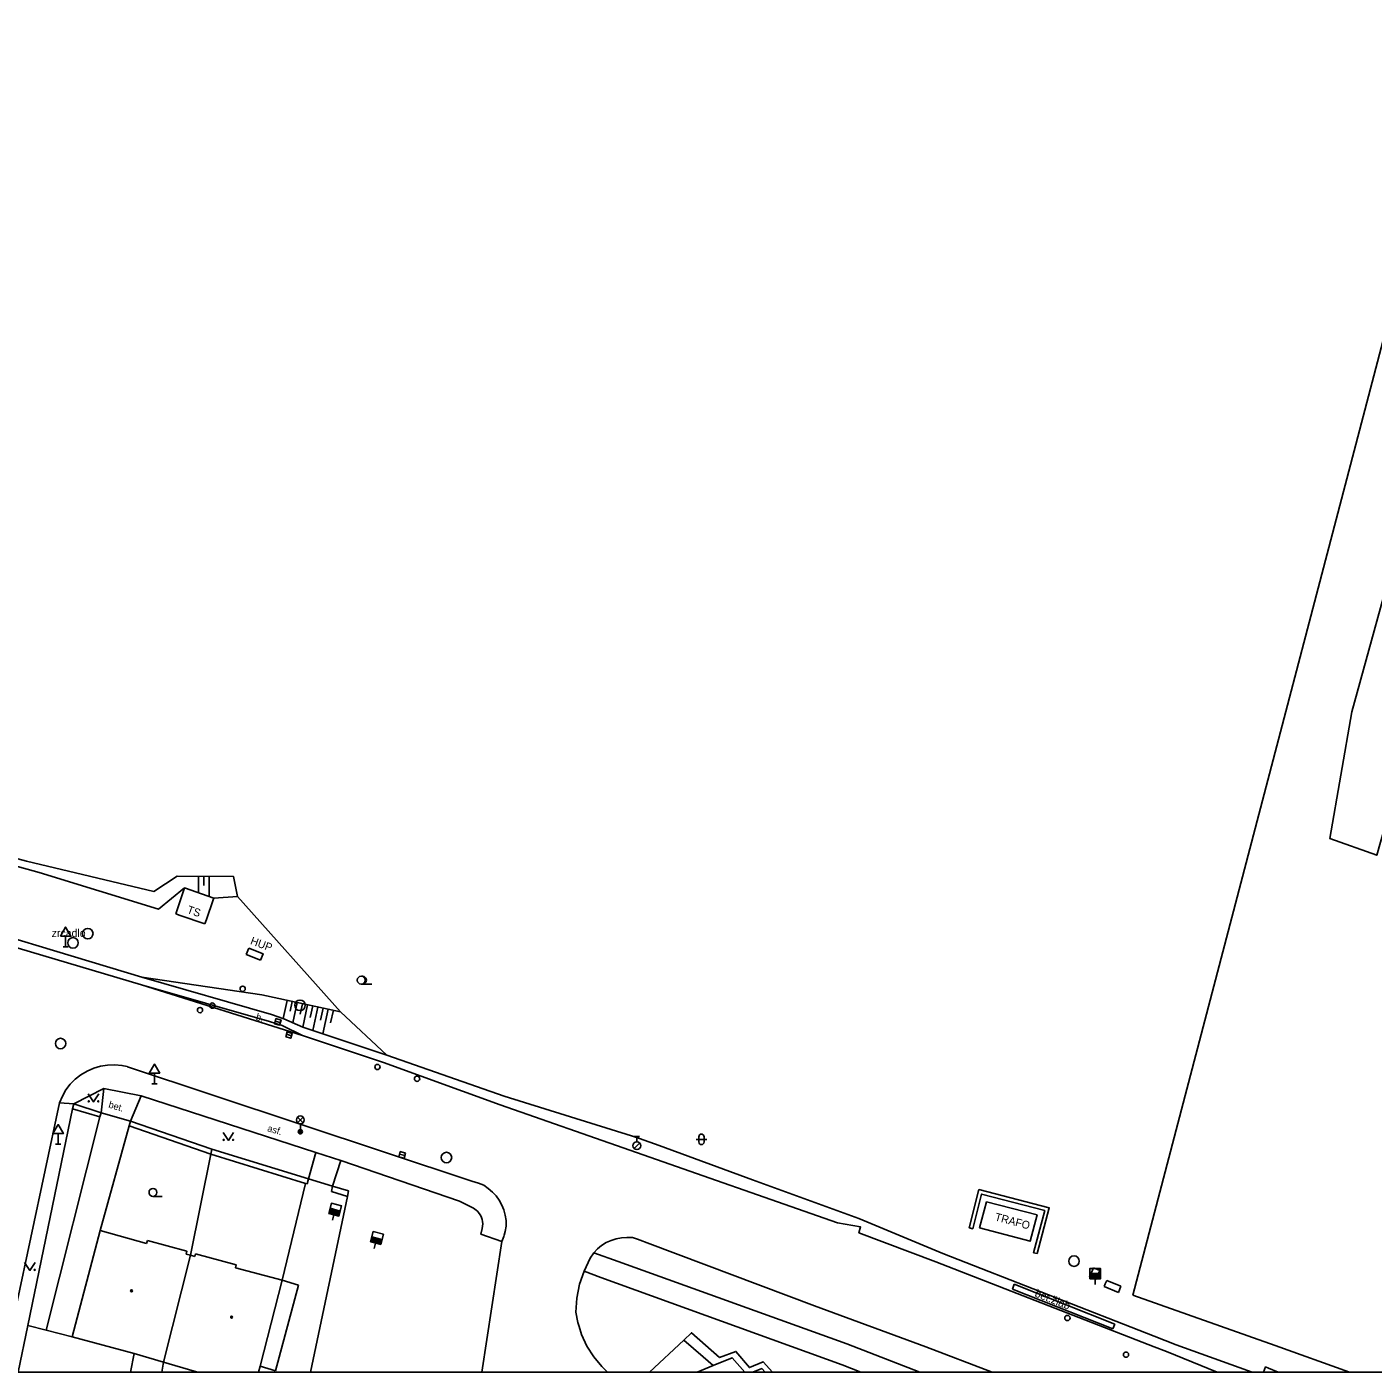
# Model space of a CAD drawing. Extents: x -599951 to -598963, y -1164095 to -1162939.
# Drawn here: x -599607.3 to -599479.2, y -1164094.7 to -1163966.7 of the extents above; entities that cross this region are included whole.
import ezdxf

# ---------------------------------------------------------------- set-up
doc = ezdxf.new("R2010")
doc.units = 0
for name, color, linetype in [('Level 10', 7, 'Continuous'), ('Level 11', 7, 'Continuous'), ('Level 14', 7, 'Continuous'), ('Level 15', 7, 'Continuous'), ('Level 21', 7, 'Continuous'), ('Level 24', 7, 'Continuous'), ('Level 27', 7, 'Continuous'), ('Level 28', 7, 'Continuous'), ('Level 33', 7, 'Continuous'), ('Level 34', 7, 'Continuous'), ('Level 36', 7, 'Continuous'), ('Level 39', 7, 'Continuous'), ('Level 40', 7, 'Continuous'), ('Level 41', 7, 'Continuous'), ('Level 42', 7, 'Continuous'), ('Level 5', 7, 'Continuous'), ('Level 6', 7, 'Continuous'), ('Level 7', 7, 'Continuous'), ('Level 8', 7, 'Continuous'), ('Vrstva 53', 7, 'Continuous')]:
    doc.layers.add(name, color=color, linetype=linetype)

msp = doc.modelspace()

# ---------------------------------------------------------------- linework, layer by layer
at = {"layer": 'Level 10'}
for p, q in [((-599609.64, -1164094.69), (-599604.19, -1164069.07)), ((-599563.98, -1164094.69), (-599562.08, -1164082.28))]:
    msp.add_line(p, q, dxfattribs=at)
for points in [[(-599638.89, -1164045.17), (-599617.56, -1164051.55), (-599596.39, -1164057.85), (-599581.06, -1164062.67), (-599573.37, -1164065.22)], [(-599604.19, -1164069.07), (-599603.92, -1164068.44), (-599603.58, -1164067.85), (-599603.17, -1164067.31), (-599602.69, -1164066.82), (-599602.15, -1164066.4), (-599601.57, -1164066.05), (-599600.94, -1164065.78), (-599600.29, -1164065.59), (-599599.61, -1164065.48), (-599598.93, -1164065.46)], [(-599598.93, -1164065.46), (-599598.25, -1164065.52), (-599597.76, -1164065.62), (-599597.71, -1164065.64), (-599564.95, -1164076.52), (-599564.31, -1164076.73), (-599563.81, -1164076.92)], [(-599573.37, -1164065.22), (-599562.25, -1164069.26), (-599549.91, -1164073.58), (-599530.13, -1164080.49), (-599527.95, -1164080.88), (-599528.11, -1164081.43), (-599520.79, -1164084.2), (-599500, -1164092.28), (-599498.82, -1164092.74), (-599494.02, -1164094.69)], [(-599563.81, -1164076.92), (-599563.38, -1164077.23), (-599562.98, -1164077.56), (-599562.63, -1164077.93), (-599562.33, -1164078.35), (-599562.08, -1164078.8), (-599561.89, -1164079.27), (-599561.76, -1164079.77), (-599561.69, -1164080.28), (-599561.69, -1164080.8), (-599561.76, -1164081.31), (-599561.86, -1164081.68), (-599561.89, -1164081.8), (-599562.08, -1164082.28)], [(-599553.35, -1164083.34), (-599553, -1164082.97), (-599552.6, -1164082.65), (-599552.16, -1164082.38), (-599551.7, -1164082.17), (-599551.21, -1164082.02), (-599550.7, -1164081.93), (-599550.19, -1164081.9), (-599549.66, -1164081.9)], [(-599515.43, -1164094.69), (-599521.74, -1164092.28), (-599532.33, -1164088.4), (-599547.99, -1164082.49), (-599549.19, -1164082.04), (-599549.66, -1164081.9)], [(-599554.27, -1164085.1), (-599553.67, -1164083.87), (-599553.35, -1164083.34)], [(-599554.27, -1164085.1), (-599554.69, -1164086.34), (-599554.95, -1164087.65), (-599555.05, -1164088.98), (-599554.86, -1164089.97), (-599554.74, -1164090.36), (-599554.5, -1164091.12), (-599553.99, -1164092.22), (-599553.35, -1164093.24), (-599552.58, -1164094.18), (-599552.04, -1164094.69)]]:
    msp.add_lwpolyline(points, dxfattribs=at)
at = {"layer": 'Level 11'}
for p, q in [((-599548.05, -1164094.69), (-599544.77, -1164091.65)), ((-599543.5, -1164094.69), (-599541.97, -1164094.07)), ((-599489.12, -1164094.32), (-599488.19, -1164094.69))]:
    msp.add_line(p, q, dxfattribs=at)
for points in [[(-599477.64, -1164041.35), (-599478.82, -1164045.51), (-599483.27, -1164043.92), (-599481.2, -1164031.86), (-599476.6, -1164015.19), (-599469.61, -1163987.57), (-599469.77, -1163986.77), (-599466.12, -1163972.33)], [(-599596.35, -1164057.12), (-599617.6, -1164050.7), (-599625.85, -1164047.89), (-599634, -1164045.88), (-599638.54, -1164044.56), (-599660.54, -1164037.91), (-599660.28, -1164036.8), (-599661.4, -1164036.53), (-599661.73, -1164037.61), (-599663.03, -1164037.18), (-599677.51, -1164032.87)], [(-599596.35, -1164057.12), (-599584.02, -1164060.68), (-599582.83, -1164061.07), (-599581.03, -1164061.88)], [(-599596.39, -1164057.85), (-599584.21, -1164061.33), (-599583.01, -1164061.7), (-599581.06, -1164062.67)], [(-599581.03, -1164061.88), (-599573.05, -1164064.54)], [(-599490.68, -1164094.69), (-599491.12, -1164094.53), (-599497.91, -1164092.1), (-599500, -1164091.28), (-599520.12, -1164083.41), (-599528.11, -1164080.07), (-599538.23, -1164076.39), (-599547.12, -1164073.14), (-599548.98, -1164072.47), (-599549.76, -1164072.22), (-599561.87, -1164068.45), (-599573.05, -1164064.54)], [(-599602.84, -1164069.18), (-599599.98, -1164067.7)], [(-599599.98, -1164067.7), (-599600.24, -1164070.02)], [(-599596.42, -1164068.41), (-599599.98, -1164067.7)], [(-599597.44, -1164070.83), (-599596.42, -1164068.41)], [(-599579.81, -1164073.79), (-599596.42, -1164068.41)], [(-599602.84, -1164069.18), (-599604.19, -1164069.07)], [(-599600.34, -1164070.42), (-599605.46, -1164090.71)], [(-599600.33, -1164081.21), (-599597.55, -1164071.25)], [(-599589.71, -1164073.49), (-599589.8, -1164073.96)], [(-599580.5, -1164076.3), (-599579.81, -1164073.79)], [(-599577.42, -1164074.55), (-599579.81, -1164073.79)], [(-599577.42, -1164074.55), (-599578.2, -1164077)], [(-599562.08, -1164082.28), (-599564.09, -1164081.57), (-599563.96, -1164081.02), (-599563.92, -1164080.81), (-599563.91, -1164080.6), (-599563.92, -1164080.38), (-599563.96, -1164080.17), (-599564.03, -1164079.97), (-599564.12, -1164079.77), (-599564.24, -1164079.59), (-599564.37, -1164079.43), (-599564.53, -1164079.28), (-599564.79, -1164079.11), (-599566.13, -1164078.44), (-599577.42, -1164074.55)], [(-599580.77, -1164076.75), (-599582.99, -1164085.96)], [(-599511.14, -1164083.42), (-599509.99, -1164079.07), (-599516.68, -1164077.33), (-599517.61, -1164080.97)], [(-599553.35, -1164083.34), (-599551.02, -1164084.18), (-599529.24, -1164092.02), (-599522.31, -1164094.69)], [(-599527.92, -1164094.69), (-599529.71, -1164094.01), (-599552.68, -1164085.68), (-599554.27, -1164085.1)], [(-599506.15, -1164085.65), (-599505.77, -1164084.77)], [(-599505.77, -1164084.77), (-599505.17, -1164085.02)], [(-599505.17, -1164085.02), (-599505.55, -1164085.9)], [(-599582.99, -1164085.96), (-599585.1, -1164094.12)], [(-599513.33, -1164086.32), (-599513.48, -1164086.79)], [(-599503.74, -1164090.13), (-599513.33, -1164086.32)], [(-599505.55, -1164085.9), (-599506.15, -1164085.65)], [(-599513.48, -1164086.79), (-599503.92, -1164090.59)], [(-599502.02, -1164087.39), (-599488.48, -1164092.18), (-599481.4, -1164094.69)], [(-599607.21, -1164090.26), (-599605.46, -1164090.71), (-599602.98, -1164091.35)], [(-599503.74, -1164090.13), (-599503.92, -1164090.59)], [(-599541.36, -1164093.32), (-599544.04, -1164090.96), (-599544.77, -1164091.65)], [(-599544.77, -1164091.65), (-599542.94, -1164093.23), (-599541.97, -1164094.07)], [(-599536.32, -1164094.69), (-599537.22, -1164093.72), (-599538.52, -1164094.27), (-599539.81, -1164092.73), (-599541.36, -1164093.32)], [(-599541.97, -1164094.07), (-599540.18, -1164093.33), (-599538.96, -1164094.69)], [(-599538.19, -1164094.69), (-599537.33, -1164094.36), (-599537.02, -1164094.69)], [(-599489.59, -1164094.69), (-599489.4, -1164094.21), (-599489.12, -1164094.32)]]:
    msp.add_lwpolyline(points, dxfattribs=at)
at = {"layer": 'Level 14'}
for points in [[(-599587.26, -1164049.45), (-599587.64, -1164047.53), (-599593, -1164047.51), (-599595.2, -1164048.95), (-599607.33, -1164046.09), (-599623.03, -1164041.85), (-599630.68, -1164039.44), (-599631.31, -1164034.32), (-599634.48, -1164028.79), (-599654.8, -1164024.23), (-599656.89, -1164030.03), (-599659.52, -1164029.78), (-599661.32, -1164033.38), (-599670.35, -1164030.9), (-599677.62, -1164029.52), (-599680.11, -1164029.17)], [(-599660.28, -1164036.8), (-599658.89, -1164031.33), (-599656.17, -1164031.26), (-599653.98, -1164025.92), (-599637.13, -1164031.36), (-599632.73, -1164035.88), (-599630.79, -1164039.78), (-599623.09, -1164042.46), (-599606.14, -1164047.14), (-599594.76, -1164050.63), (-599592.29, -1164048.62)], [(-599589.51, -1164049.6), (-599587.26, -1164049.45)], [(-599596.35, -1164057.12), (-599584.92, -1164058.81), (-599577.45, -1164060.42)]]:
    msp.add_lwpolyline(points, dxfattribs=at)
at = {"layer": 'Level 15'}
for points in [[(-599590.95, -1164047.52), (-599590.96, -1164049.09)], [(-599590.45, -1164047.52), (-599590.45, -1164048.39)], [(-599589.95, -1164047.52), (-599589.96, -1164049.44)], [(-599582.53, -1164059.32), (-599582.9, -1164061.05)], [(-599582.04, -1164059.43), (-599582.24, -1164060.34)], [(-599581.56, -1164059.54), (-599581.97, -1164061.46)], [(-599581.07, -1164059.64), (-599581.29, -1164060.65)], [(-599580.58, -1164059.75), (-599581.04, -1164061.88)], [(-599580.09, -1164059.85), (-599580.33, -1164060.94)], [(-599579.6, -1164059.96), (-599580.08, -1164062.2)], [(-599579.11, -1164060.06), (-599579.36, -1164061.21)], [(-599578.62, -1164060.17), (-599579.13, -1164062.51)], [(-599578.13, -1164060.27), (-599578.39, -1164061.47)]]:
    msp.add_lwpolyline(points, dxfattribs=at)
at = {"layer": 'Level 21'}
for points in [[(-599587.26, -1164049.45), (-599577.45, -1164060.42)], [(-599577.45, -1164060.42), (-599573.05, -1164064.54)]]:
    msp.add_lwpolyline(points, dxfattribs=at)
at = {"layer": 'Level 24'}
for points in [[(-599586.18, -1164054.36), (-599586.43, -1164054.96)], [(-599586.18, -1164054.36), (-599584.82, -1164054.88), (-599585.07, -1164055.51)], [(-599586.43, -1164054.96), (-599585.07, -1164055.51)], [(-599504.76, -1164086.55), (-599504.66, -1164086.3)], [(-599503.41, -1164087.11), (-599504.76, -1164086.55)], [(-599504.66, -1164086.3), (-599504.52, -1164085.97)], [(-599504.52, -1164085.97), (-599503.17, -1164086.53)], [(-599503.17, -1164086.53), (-599503.31, -1164086.86)], [(-599503.31, -1164086.86), (-599503.41, -1164087.11)]]:
    msp.add_lwpolyline(points, dxfattribs=at)
at = {"layer": 'Level 27'}
for p, q in [((-599583.66, -1164061.3), (-599583.18, -1164061.44)), ((-599582.59, -1164062.55), (-599582.11, -1164062.69)), ((-599571.82, -1164073.96), (-599571.34, -1164074.1))]:
    msp.add_line(p, q, dxfattribs=at)
for points in [[(-599583.73, -1164061.54), (-599583.25, -1164061.68), (-599583.11, -1164061.2), (-599583.59, -1164061.06)], [(-599582.66, -1164062.78), (-599582.19, -1164062.93), (-599582.04, -1164062.46), (-599582.51, -1164062.31)], [(-599571.89, -1164074.21), (-599571.4, -1164074.34), (-599571.27, -1164073.85), (-599571.76, -1164073.72)]]:
    msp.add_lwpolyline(points, close=True, dxfattribs=at)
for centre in [(-599602.91, -1164053.85), (-599601.5, -1164052.97), (-599581.3, -1164059.79), (-599604.09, -1164063.43), (-599567.36, -1164074.28), (-599507.63, -1164084.14)]:
    msp.add_circle(centre, 0.5, dxfattribs=at)
at = {"layer": 'Level 28'}
for p, q in [((-599549.49, -1164072.27), (-599548.99, -1164072.27)), ((-599549.24, -1164072.77), (-599549.24, -1164072.27)), ((-599549.5, -1164073.42), (-599548.97, -1164072.89)), ((-599578.56, -1164079.55), (-599577.59, -1164079.8)), ((-599578.54, -1164079.5), (-599577.58, -1164079.75)), ((-599578.53, -1164079.45), (-599577.56, -1164079.7)), ((-599578.52, -1164079.4), (-599577.55, -1164079.66)), ((-599578.51, -1164079.36), (-599577.54, -1164079.61)), ((-599578.49, -1164079.31), (-599577.53, -1164079.56)), ((-599578.48, -1164079.26), (-599577.51, -1164079.51)), ((-599578.47, -1164079.21), (-599577.5, -1164079.46)), ((-599578.46, -1164079.16), (-599577.49, -1164079.41)), ((-599578.44, -1164079.11), (-599577.48, -1164079.37)), ((-599578.09, -1164079.72), (-599578.22, -1164080.24)), ((-599574.58, -1164082.25), (-599573.61, -1164082.5)), ((-599574.56, -1164082.2), (-599573.6, -1164082.45)), ((-599574.55, -1164082.15), (-599573.58, -1164082.41)), ((-599574.54, -1164082.1), (-599573.57, -1164082.36)), ((-599574.53, -1164082.06), (-599573.56, -1164082.31)), ((-599574.51, -1164082.01), (-599573.55, -1164082.26)), ((-599574.5, -1164081.96), (-599573.53, -1164082.21)), ((-599574.49, -1164081.91), (-599573.52, -1164082.16)), ((-599574.48, -1164081.86), (-599573.51, -1164082.11)), ((-599574.46, -1164081.81), (-599573.5, -1164082.07)), ((-599574.11, -1164082.42), (-599574.24, -1164082.94)), ((-599506.12, -1164085.33), (-599505.12, -1164085.33)), ((-599506.12, -1164085.38), (-599505.12, -1164085.38)), ((-599506.12, -1164085.43), (-599505.12, -1164085.43)), ((-599506.12, -1164085.48), (-599505.12, -1164085.48)), ((-599506.12, -1164085.53), (-599505.12, -1164085.53)), ((-599506.12, -1164085.58), (-599505.12, -1164085.58)), ((-599506.12, -1164085.63), (-599505.12, -1164085.63)), ((-599506.12, -1164085.68), (-599505.12, -1164085.68)), ((-599506.12, -1164085.73), (-599505.12, -1164085.73)), ((-599506.12, -1164085.78), (-599505.12, -1164085.78)), ((-599505.62, -1164085.83), (-599505.62, -1164086.36))]:
    msp.add_line(p, q, dxfattribs=at)
for points in [[(-599578.57, -1164079.6), (-599577.6, -1164079.85), (-599577.35, -1164078.88), (-599578.32, -1164078.63)], [(-599574.59, -1164082.3), (-599573.62, -1164082.55), (-599573.37, -1164081.58), (-599574.34, -1164081.33)], [(-599506.12, -1164085.83), (-599505.12, -1164085.83), (-599505.12, -1164084.83), (-599506.12, -1164084.83)]]:
    msp.add_lwpolyline(points, close=True, dxfattribs=at)
for centre, radius in [((-599586.76, -1164058.22), 0.25), ((-599589.65, -1164059.82), 0.25), ((-599590.82, -1164060.25), 0.25), ((-599573.93, -1164065.66), 0.25), ((-599570.16, -1164066.78), 0.25), ((-599549.24, -1164073.15), 0.375), ((-599508.26, -1164089.55), 0.25), ((-599502.68, -1164093.04), 0.25)]:
    msp.add_circle(centre, radius, dxfattribs=at)
at = {"layer": 'Level 33'}
for p, q in [((-599581.53, -1164070.97), (-599581, -1164070.44)), ((-599581.53, -1164070.44), (-599581, -1164070.97)), ((-599581.27, -1164071.08), (-599581.27, -1164071.83))]:
    msp.add_line(p, q, dxfattribs=at)
for centre, radius in [((-599581.27, -1164070.7), 0.375), ((-599581.27, -1164071.83), 0.2), ((-599581.27, -1164071.83), 0.145), ((-599581.27, -1164071.83), 0.0876)]:
    msp.add_circle(centre, radius, dxfattribs=at)
at = {"layer": 'Level 34'}
for p, q in [((-599603.61, -1164053.21), (-599603.61, -1164054.23)), ((-599603.86, -1164054.23), (-599603.36, -1164054.23)), ((-599595.41, -1164067.26), (-599594.91, -1164067.26)), ((-599595.16, -1164066.24), (-599595.16, -1164067.26)), ((-599604.32, -1164072), (-599604.32, -1164073.02)), ((-599604.57, -1164073.02), (-599604.07, -1164073.02))]:
    msp.add_line(p, q, dxfattribs=at)
for points in [[(-599604.11, -1164053.21), (-599603.11, -1164053.21), (-599603.61, -1164052.35)], [(-599595.66, -1164066.24), (-599594.66, -1164066.24), (-599595.16, -1164065.38)], [(-599604.82, -1164072), (-599603.82, -1164072), (-599604.32, -1164071.14)]]:
    msp.add_lwpolyline(points, close=True, dxfattribs=at)
at = {"layer": 'Level 36'}
for p, q in [((-599575.48, -1164057.77), (-599574.48, -1164057.77)), ((-599543.59, -1164072.55), (-599542.59, -1164072.55)), ((-599543.34, -1164072.3), (-599543.34, -1164072.8)), ((-599542.84, -1164072.3), (-599542.84, -1164072.8)), ((-599595.3, -1164077.98), (-599594.43, -1164077.98))]:
    msp.add_line(p, q, dxfattribs=at)
for points in [[(-599601.46, -1164068.23), (-599600.96, -1164068.98), (-599600.46, -1164068.23)], [(-599588.62, -1164071.9), (-599588.12, -1164072.65), (-599587.62, -1164071.9)], [(-599607.51, -1164084.27), (-599607.01, -1164085.02), (-599606.51, -1164084.27)]]:
    msp.add_lwpolyline(points, dxfattribs=at)
for centre, radius in [((-599575.48, -1164057.4), 0.375), ((-599601.41, -1164068.93), 0.05), ((-599600.51, -1164068.93), 0.05), ((-599588.57, -1164072.6), 0.05), ((-599587.67, -1164072.6), 0.05), ((-599595.3, -1164077.6), 0.375), ((-599606.56, -1164084.97), 0.05)]:
    msp.add_circle(centre, radius, dxfattribs=at)
for centre, radius, start, end in [((-599575.36, -1164057.4), 0.375, 260.4059, 99.5941), ((-599543.09, -1164072.3), 0.25, 0, 180), ((-599543.09, -1164072.8), 0.25, 180, 0)]:
    msp.add_arc(centre, radius, start, end, dxfattribs=at)
at = {"layer": 'Level 39'}
for centre, radius in [((-599597.34, -1164086.96), 0.09), ((-599597.34, -1164086.96), 0.0398), ((-599587.81, -1164089.46), 0.09), ((-599587.81, -1164089.46), 0.0398)]:
    msp.add_circle(centre, radius, dxfattribs=at)
at = {"layer": 'Level 5'}
for p, q in [((-599597.09, -1164092.94), (-599597.45, -1164094.69)), ((-599594.28, -1164093.76), (-599594.46, -1164094.69)), ((-599585.1, -1164094.12), (-599585.26, -1164094.69)), ((-599591.38, -1164094.6), (-599591.4, -1164094.69)), ((-599591.38, -1164094.6), (-599591.03, -1164094.69))]:
    msp.add_line(p, q, dxfattribs=at)
for points in [[(-599593.12, -1164051.08), (-599592.29, -1164048.62)], [(-599592.29, -1164048.62), (-599589.51, -1164049.6)], [(-599589.51, -1164049.6), (-599589.56, -1164049.75), (-599590.21, -1164051.63), (-599590.37, -1164052.05)], [(-599590.37, -1164052.05), (-599592.71, -1164051.23), (-599593.12, -1164051.08)], [(-599515.96, -1164078.48), (-599511.15, -1164079.74), (-599511.81, -1164082.25), (-599516.64, -1164080.97)], [(-599516.64, -1164080.97), (-599515.96, -1164078.48)], [(-599600.33, -1164081.21), (-599602.98, -1164091.35)], [(-599600.33, -1164081.21), (-599595.9, -1164082.46)], [(-599595.82, -1164082.17), (-599595.9, -1164082.46)], [(-599595.82, -1164082.17), (-599592.06, -1164083.2)], [(-599591.72, -1164083.58), (-599594.28, -1164093.76)], [(-599592.06, -1164083.2), (-599592.13, -1164083.46)], [(-599592.13, -1164083.46), (-599591.72, -1164083.58)], [(-599591.72, -1164083.58), (-599591.31, -1164083.71)], [(-599591.24, -1164083.43), (-599591.31, -1164083.71)], [(-599591.24, -1164083.43), (-599587.38, -1164084.49)], [(-599587.38, -1164084.49), (-599587.43, -1164084.78)], [(-599587.43, -1164084.78), (-599582.99, -1164085.96)], [(-599581.44, -1164086.42), (-599583.63, -1164094.59)], [(-599582.99, -1164085.96), (-599581.44, -1164086.42)], [(-599602.98, -1164091.35), (-599597.09, -1164092.94)], [(-599597.09, -1164092.94), (-599594.28, -1164093.76)], [(-599594.28, -1164093.76), (-599591.38, -1164094.6)], [(-599585.1, -1164094.12), (-599583.63, -1164094.59)]]:
    msp.add_lwpolyline(points, dxfattribs=at)
at = {"layer": 'Level 6'}
msp.add_lwpolyline([(-599597.44, -1164070.83), (-599600.24, -1164070.02)], dxfattribs=at)
at = {"layer": 'Level 7'}
for p, q in [((-599576.79, -1164077.98), (-599580.31, -1164094.69)), ((-599608.12, -1164094.69), (-599607.21, -1164090.26))]:
    msp.add_line(p, q, dxfattribs=at)
for points in [[(-599470.69, -1163967.82), (-599502.02, -1164087.39)], [(-599607.21, -1164090.26), (-599602.97, -1164069.63)], [(-599602.97, -1164069.63), (-599602.84, -1164069.18)], [(-599602.97, -1164069.63), (-599600.34, -1164070.42)], [(-599600.24, -1164070.02), (-599602.84, -1164069.18)], [(-599600.24, -1164070.02), (-599602.84, -1164069.18)], [(-599600.24, -1164070.02), (-599600.34, -1164070.42)], [(-599597.44, -1164070.83), (-599597.55, -1164071.25)], [(-599597.55, -1164071.25), (-599589.8, -1164073.96)], [(-599589.71, -1164073.49), (-599597.44, -1164070.83)], [(-599589.71, -1164073.49), (-599597.44, -1164070.83)], [(-599580.5, -1164076.3), (-599589.71, -1164073.49)], [(-599589.8, -1164073.96), (-599591.72, -1164083.58)], [(-599589.8, -1164073.96), (-599580.77, -1164076.75), (-599580.63, -1164076.79)], [(-599580.5, -1164076.3), (-599580.63, -1164076.79)], [(-599578.2, -1164077), (-599578.31, -1164077.51)], [(-599578.31, -1164077.51), (-599576.79, -1164077.98)], [(-599576.68, -1164077.46), (-599578.2, -1164077)], [(-599576.68, -1164077.46), (-599576.79, -1164077.98)], [(-599517.61, -1164080.97), (-599517.27, -1164081.06), (-599516.43, -1164077.76), (-599510.42, -1164079.32), (-599511.48, -1164083.34), (-599511.14, -1164083.42)]]:
    msp.add_lwpolyline(points, dxfattribs=at)
at = {"layer": 'Level 8'}
msp.add_lwpolyline([(-599580.5, -1164076.3), (-599578.2, -1164077)], dxfattribs=at)
at = {"layer": 'Vrstva 53'}
msp.add_lwpolyline([(-599951.12, -1164094.69), (-598963.21, -1164094.69), (-598963.21, -1162939.4), (-599951.12, -1162939.4)], close=True, dxfattribs=at)

# ---------------------------------------------------------------- texts
at = {"layer": 'Level 40'}
for s, rotation, p in [('b.', 343, (-599585.56, -1164061.16)), ('bet.', 343, (-599599.58, -1164069.51)), ('asf.', 343.54, (-599584.46, -1164071.76))]:
    msp.add_text(s, height=0.65, rotation=rotation, dxfattribs=at).set_placement(p)
at = {"layer": 'Level 41'}
for s, rotation, p in [('TS', 341, (-599592.12, -1164050.99)), ('HUP', 339.7322, (-599586.09, -1164053.95)), ('TRAFO', 345, (-599515.22, -1164080.25))]:
    msp.add_text(s, height=0.75, rotation=rotation, dxfattribs=at).set_placement(p)
at = {"layer": 'Level 42'}
msp.add_text('zrcadlo', height=0.75, dxfattribs=at).set_placement((-599604.94, -1164053.29))
msp.add_text('bet.žlab', height=0.75, rotation=338.3124, dxfattribs=at).set_placement((-599511.43, -1164087.48))

doc.saveas('drawing.dxf')
